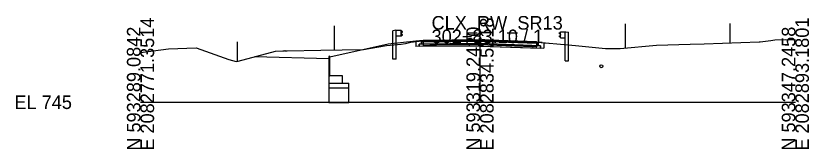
# Model space of a CAD drawing. Extents: x -26 to 2138, y -10 to 4518.
# Drawn here: x -25.7 to 137.8, y 3990.3 to 4017.8 of the extents above; entities that cross this region are included whole.
import ezdxf

# ---------------------------------------------------------------- set-up
doc = ezdxf.new("R2010")
doc.units = 0
for name, color, linetype in [('GK_Cells', 7, 'Continuous'), ('MD_P_Surface_Aggregate_Base', 7, 'Continuous'), ('MD_P_Surface_Asphalt_Concrete_Base', 7, 'Continuous'), ('MD_P_Surface_Asphalt_Concrete_Intermediate_Course', 7, 'Continuous'), ('MD_P_Surface_Asphalt_Concrete_Surface_Course', 7, 'Continuous'), ('MD_P_Surface_Non-Reinforced_Concrete_Pavement', 7, 'Continuous'), ('MD_X_Asphalt_Pavement', 7, 'Continuous'), ('RD_P_Cells', 7, 'Continuous'), ('RW_P_Esmt_SH', 7, 'Continuous'), ('RW_X_Esmt_SH', 7, 'Continuous'), ('SC_Scratch1', 7, 'Continuous'), ('UT_X_Water', 7, 'Continuous'), ('XS_P_Excavation_Limits', 7, 'Continuous'), ('XS_P_Finished_Grade', 7, 'Continuous'), ('XS_P_Subgrade', 7, 'Continuous'), ('XS_X_Ground_Line', 7, 'Continuous')]:
    doc.layers.add(name, color=color, linetype=linetype)

msp = doc.modelspace()

# ---------------------------------------------------------------- linework, layer by layer
at = {"layer": 'GK_Cells'}
for p, q in [((70, 4000), (70, 4015)), ((0, 4000), (70, 4000)), ((70, 4000), (135, 4000))]:
    msp.add_line(p, q, dxfattribs=at)
at = {"layer": 'MD_P_Surface_Aggregate_Base'}
for points in [[(70, 4012.11), (70, 4011.61), (57.45, 4011.48), (57.45, 4011.98), (70, 4012.11)], [(70, 4012.11), (70, 4011.61), (82.48, 4011.18), (82.48, 4011.68), (70, 4012.11)]]:
    msp.add_lwpolyline(points, dxfattribs=at)
at = {"layer": 'MD_P_Surface_Asphalt_Concrete_Base'}
for points in [[(70, 4012.61), (70, 4012.11), (57.95, 4011.99), (57.95, 4012.49), (70, 4012.61)], [(70, 4012.61), (70, 4012.11), (81.98, 4011.69), (81.98, 4012.19), (81.65, 4012.2), (70, 4012.61)]]:
    msp.add_lwpolyline(points, dxfattribs=at)
at = {"layer": 'MD_P_Surface_Asphalt_Concrete_Intermediate_Course'}
for points in [[(70, 4012.76), (70, 4012.61), (58.28, 4012.49), (58.28, 4012.64), (70, 4012.76)], [(70, 4012.76), (70, 4012.61), (81.65, 4012.2), (81.65, 4012.35), (70, 4012.76)]]:
    msp.add_lwpolyline(points, dxfattribs=at)
at = {"layer": 'MD_P_Surface_Asphalt_Concrete_Surface_Course'}
for points in [[(70, 4012.86), (70, 4012.76), (58.28, 4012.64), (58.28, 4012.74), (70, 4012.86)], [(70, 4012.86), (70, 4012.76), (81.65, 4012.35), (81.65, 4012.45), (70, 4012.86)]]:
    msp.add_lwpolyline(points, dxfattribs=at)
at = {"layer": 'MD_P_Surface_Non-Reinforced_Concrete_Pavement'}
for points in [[(38.85, 4009.46), (38.85, 4005.46), (39.01, 4005.46), (39.01, 4009.49), (38.85, 4009.46)], [(40.38, 4005.46), (39.94, 4005.46), (38.85, 4005.46), (38.85, 4004.44), (38.85, 4003.96), (39.63, 4003.96), (40.38, 4003.96), (41.66, 4003.96), (41.66, 4004.27), (41.66, 4005.46), (40.38, 4005.46)]]:
    msp.add_lwpolyline(points, dxfattribs=at)
at = {"layer": 'MD_X_Asphalt_Pavement'}
msp.add_lwpolyline([(58.29, 4012.7), (58.29, 4011.74), (58.58, 4011.75), (59.66, 4011.8), (61, 4011.82), (70.07, 4011.9), (71.57, 4011.84), (80.83, 4011.5), (81.6, 4011.45), (81.68, 4011.45), (81.68, 4012.41), (81.6, 4012.41), (80.83, 4012.46), (71.57, 4012.8), (70.07, 4012.86), (61, 4012.78), (59.66, 4012.76), (58.58, 4012.71), (58.29, 4012.7)], dxfattribs=at)
at = {"layer": 'RD_P_Cells'}
for p, q in [((52.1, 4014.77), (52.05, 4014.75)), ((52.05, 4008.86), (52.05, 4014.75)), ((52.64, 4014.86), (52.1, 4014.77)), ((52.72, 4014.81), (52.64, 4014.86)), ((53.72, 4014.81), (52.72, 4014.81)), ((52.72, 4008.86), (52.72, 4014.81)), ((53.72, 4013.63), (53.72, 4014.81)), ((53.81, 4014.72), (53.72, 4014.73)), ((53.72, 4013.63), (52.72, 4013.63)), ((53.72, 4013.71), (53.81, 4013.73)), ((53.73, 4014.22), (53.73, 4014.27)), ((53.73, 4014.17), (53.73, 4014.22)), ((53.76, 4014.33), (53.97, 4014.47)), ((53.97, 4013.97), (53.76, 4014.11)), ((53.97, 4014.6), (53.81, 4014.72)), ((53.81, 4013.73), (53.97, 4013.84)), ((86.33, 4014.31), (86.49, 4014.42)), ((86.54, 4014.03), (86.33, 4014.18)), ((86.33, 4013.67), (86.54, 4013.81)), ((86.49, 4013.43), (86.33, 4013.54)), ((86.49, 4014.42), (86.58, 4014.43)), ((86.58, 4013.41), (86.49, 4013.43)), ((86.57, 4013.92), (86.57, 4013.97)), ((86.57, 4013.88), (86.57, 4013.92)), ((86.58, 4013.33), (86.58, 4014.52)), ((86.58, 4014.52), (87.58, 4014.52)), ((86.58, 4013.33), (87.58, 4013.33)), ((87.58, 4014.52), (87.66, 4014.56)), ((87.58, 4008.56), (87.58, 4014.52)), ((87.66, 4014.56), (88.2, 4014.48)), ((88.2, 4014.48), (88.25, 4014.46)), ((88.25, 4008.56), (88.25, 4014.46)), ((52.72, 4008.86), (52.05, 4008.86)), ((87.58, 4008.56), (88.25, 4008.56))]:
    msp.add_line(p, q, dxfattribs=at)
for points in [[(53.74, 4014.28), (53.74, 4014.16), (53.73, 4014.16), (53.73, 4014.28)], [(53.74, 4014.25), (53.74, 4014.19), (53.76, 4014.19), (53.76, 4014.25)], [(86.56, 4013.95), (86.56, 4013.89), (86.54, 4013.89), (86.54, 4013.95)], [(86.56, 4013.98), (86.56, 4013.86), (86.57, 4013.86), (86.57, 4013.98)]]:
    msp.add_lwpolyline(points, close=True, dxfattribs=at)
for centre, start, end in [((53.81, 4014.27), 124.962, 180), ((53.81, 4014.17), 180, 235.038), ((53.92, 4014.54), 304.962, 54.7677), ((53.92, 4013.9), 304.962, 54.7677), ((86.38, 4014.24), 125.2323, 235.038), ((86.38, 4013.61), 125.2323, 235.038), ((86.49, 4013.97), 0, 55.038), ((86.49, 4013.88), 304.962, 0)]:
    msp.add_arc(centre, 0.0781, start, end, dxfattribs=at)
at = {"layer": 'RW_P_Esmt_SH'}
for p, q in [((121.57, 4012.25), (121.57, 4016.25)), ((20, 4008.45), (20, 4012.45))]:
    msp.add_line(p, q, dxfattribs=at)
at = {"layer": 'RW_X_Esmt_SH'}
for p, q in [((40, 4010.8), (40, 4015.8)), ((100, 4011.21), (100, 4016.21))]:
    msp.add_line(p, q, dxfattribs=at)
at = {"layer": 'SC_Scratch1'}
for p, q in [((58.28, 4012.74), (56.78, 4012.59)), ((70, 4012.11), (57.45, 4011.98)), ((57.45, 4011.98), (57.45, 4011.48)), ((70, 4012.61), (57.95, 4012.49)), ((57.95, 4012.49), (57.95, 4011.99)), ((70, 4012.86), (58.28, 4012.74)), ((70, 4012.76), (58.28, 4012.64)), ((58.28, 4012.74), (58.28, 4012.49)), ((70, 4012.86), (81.65, 4012.45)), ((70, 4012.76), (81.65, 4012.35)), ((70, 4012.61), (81.98, 4012.19)), ((70, 4012.11), (82.48, 4011.68)), ((81.65, 4012.45), (81.65, 4012.2)), ((81.65, 4012.45), (83.15, 4012.3)), ((81.98, 4012.19), (81.98, 4011.69)), ((82.48, 4011.68), (82.48, 4011.18))]:
    msp.add_line(p, q, dxfattribs=at)
at = {"layer": 'UT_X_Water'}
msp.add_circle((95, 4007.42), 0.3, dxfattribs=at)
at = {"layer": 'XS_P_Excavation_Limits'}
for p, q in [((38.85, 4003.96), (38.85, 3999.96)), ((41.66, 4003.96), (42.93, 4003.96)), ((42.93, 4000), (42.93, 4003.96)), ((38.85, 4002.96), (42.93, 4002.96)), ((38.85, 3999.96), (42.93, 3999.96))]:
    msp.add_line(p, q, dxfattribs=at)
at = {"layer": 'XS_P_Finished_Grade'}
for p, q in [((51.05, 4012.02), (39.01, 4009.3)), ((56.78, 4012.59), (51.05, 4012.02)), ((83.15, 4012.3), (84.12, 4012.21)), ((38.85, 4008.96), (23.47, 4009.37))]:
    msp.add_line(p, q, dxfattribs=at)
at = {"layer": 'XS_P_Subgrade'}
for p, q in [((56.78, 4012.59), (56.78, 4011.48)), ((70, 4011.61), (56.78, 4011.48)), ((70, 4011.61), (83.15, 4011.15)), ((83.15, 4012.3), (83.15, 4011.15))]:
    msp.add_line(p, q, dxfattribs=at)
at = {"layer": 'XS_X_Ground_Line'}
msp.add_lwpolyline([(0, 4010.29), (5.77, 4011), (11.49, 4011.21), (18.19, 4008.82), (18.2, 4008.81), (19.69, 4008.4), (20.14, 4008.47), (27.81, 4010.56), (29.37, 4010.63), (29.59, 4010.64), (29.66, 4010.64), (29.73, 4010.65), (29.84, 4010.64), (29.92, 4010.63), (30.07, 4010.62), (30.24, 4010.6), (37.16, 4010.75), (45.97, 4010.89), (50.71, 4011.75), (53.71, 4012), (54.62, 4012.15), (55.71, 4012.38), (58.06, 4012.65), (58.29, 4012.7), (58.58, 4012.71), (59.66, 4012.76), (61, 4012.78), (70.07, 4012.86), (71.57, 4012.8), (80.83, 4012.46), (81.6, 4012.41), (81.68, 4012.41), (83.47, 4012.26), (89.7, 4011.72), (95.89, 4011.13), (97.72, 4011.12), (98.89, 4011.12), (106.4, 4011.76), (113.33, 4011.96), (116.22, 4012.06), (127.55, 4012.46), (127.73, 4012.48), (129.91, 4012.76), (130.74, 4012.88), (132.89, 4012.93), (135, 4012.91)], dxfattribs=at)

# ---------------------------------------------------------------- texts
msp.add_text('-', height=0.0001).set_placement((0, 4000))
at = {"layer": 'GK_Cells'}
for s, p in [('E 2082771.3514', (2.8, 3990)), ('E 2082834.5218', (72.8, 3990)), ('E 2082893.1801', (137.8, 3990)), ('N 593289.0842', (0, 3990)), ('N 593319.2420', (70, 3990)), ('N 593347.2458', (135, 3990))]:
    msp.add_text(s, height=2.8, rotation=90, dxfattribs=at).set_placement(p)
for s, p in [('CLX_RW_SR13', (60, 4015)), ('302+83.10 / 1', (60, 4012.2)), ('EL 745', (-26, 3998.6))]:
    msp.add_text(s, height=2.8, dxfattribs=at).set_placement(p)

doc.saveas('drawing.dxf')
